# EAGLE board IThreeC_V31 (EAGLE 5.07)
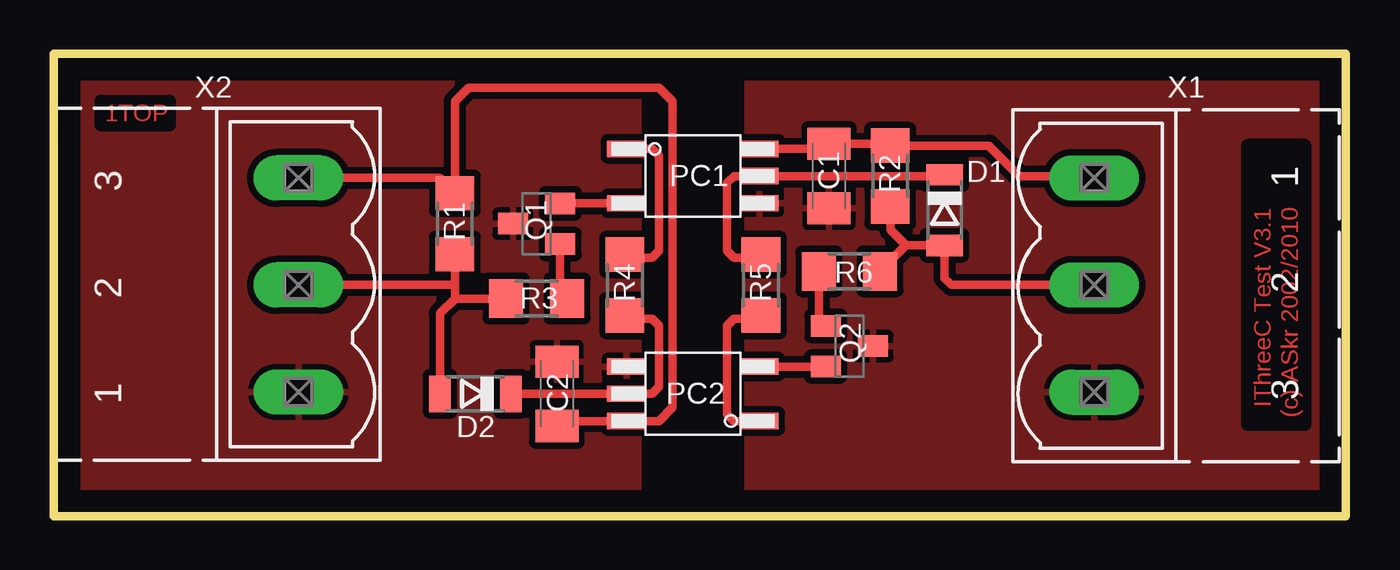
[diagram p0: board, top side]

Size 60.33 x 21.59 mm. Coordinates in mm from the lower left corner, seen from the top.
Outline: 0,21.59 60.33,21.59 60.33,0 0,0 0,21.59
Copper layers (1*16): Top 0.035mm / dielectric 1.5mm / Bottom 0.035mm
Design rules "default": minimum track width 10mil, minimum drill 24mil, track to track 8mil, track to pad 8mil, pad to pad 8mil, via to via 8mil, smd to smd 8mil, copper to edge 40mil, drill to drill 8mil, minimum pad ring 10mil, minimum via ring 8mil, stop-mask expansion 4mil, vias tented up to drill 0mil, thermal gap 10mil
tRestrict: 8 lines

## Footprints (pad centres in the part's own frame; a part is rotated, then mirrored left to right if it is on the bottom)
C1206K = smd 1.5 x 2: 1 -1.5,0; 2 1.5,0
SOD80-R = smd 1 x 1.7: A 1.65,0; C -1.65,0
AKKI_OPTOCOUP6SMD = smd 1.778 x 0.762: 1 -3.111,1.27; 3 -3.111,-1.27; 4 3.111,-1.27; 5 3.111,0; 6 3.111,1.27
SOT23-BEC = smd 1 x 1.4: B -0.95,-1.1; C 0,1.1; E 0.95,-1.1
R1206 = smd 1.6 x 1.803: 1 -1.422,0; 2 1.422,0
AKKI_MSTBV3 = drill 1.397 long: 1 -5,0; 2 0,0; 3 5,0

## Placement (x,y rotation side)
C1  470n  [C1206K]  36.2,15.88 270 top
C2  470n  [C1206K]  23.5,5.71 270 top
D1  LL103  [SOD80-R]  41.59,14.29 270 top
D2  LL103  [SOD80-R]  19.69,5.71 180 top
PC1  TLP102  [AKKI_OPTOCOUP6SMD]  29.85,15.88 0 top
PC2  TLP102  [AKKI_OPTOCOUP6SMD]  29.85,5.71 180 top
Q1  BC807-40  [SOT23-BEC]  22.54,13.65 90 top
Q2  BC807-40  [SOT23-BEC]  37.15,7.94 270 top
R1  (*1*)  [R1206]  18.73,13.65 270 top
R2  (*1*)  [R1206]  39.05,15.88 270 top
R3  5k6  [R1206]  22.54,10.16 180 top
R4  680E  [R1206]  26.67,10.8 90 top
R5  680E  [R1206]  33.02,10.8 90 top
R6  5k6  [R1206]  37.15,11.43 180 top
X1  [AKKI_MSTBV3]  48.58,10.8 270 top
X2  [AKKI_MSTBV3]  11.43,10.8 90 top

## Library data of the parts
C1 C2 R1 R2 = rcl
D1 D2 PC1 PC2 X1 X2 = Akki
Q1 Q2 = transistor-pnp
R3 R6 = rcl; NOTE: (*1*)
R4 R5 = rcl; NOTE: (*2*)

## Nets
+UB: C2.2 PC2.6 R1.1 X2.3
+UB#2: C1.1 PC1.6 R2.1 X1.1
GNDI: C2.1 PC2.4 Q1.C X2.1
GNDO: C1.2 PC1.4 Q2.C X1.3
N$1: PC1.1 R4.2
N$2: D2.C PC2.5 R4.1
N$3: PC1.3 Q1.E
N$4: Q1.B R3.1
N$5: D2.A R1.2 R3.2 X2.2
N$6: D1.C PC1.5 R5.2
N$10: PC2.1 R5.1
N$11: PC2.3 Q2.E
N$12: Q2.B R6.2
N$13: D1.A R2.2 R6.1 X1.2

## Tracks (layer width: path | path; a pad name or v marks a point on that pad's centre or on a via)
+UB
  Top 0.406: C2.2 23.73,4.45 PC2.6 28.26,4.45 28.89,5.08 28.89,19.37 28.26,20 19.37,20 18.73,19.37 R1.1 18.01,15.8 X2.3
+UB#2
  Top 0.406: PC1.6 35.96,17.14 C1.1 38.97,17.38 R2.1 43.66,17.3 45.09,15.88 48.5,15.88 X1.1
GNDI
  pour Top (isolate 0.305): 0.64,20.95 27.3,20.95 27.3,0.63 0.64,0.63
GNDO
  pour Top (isolate 0.305): 32.38,20.95 59.69,20.95 59.69,0.63 32.38,0.63
N$1
  Top 0.406: PC1.1 27.94,17.14 28.26,16.83 28.26,12.38 27.94,12.06 26.82,12.06 R4.2
N$2
  Top 0.406: R4.1 26.84,9.21 27.94,9.21 28.26,8.89 28.26,6.03 27.94,5.71 PC2.5 D2.C
N$3
  Top 0.406: PC1.3 Q1.E
N$4
  Top 0.406: Q1.B 23.64,10.48 R3.1
N$5
  Top 0.406: X2.2 18.73,10.8 | 18.73,10.8 R1.2 | 18.73,10.16 R3.2 | 18.73,10.8 18.73,10.16 | D2.A 18.04,9.46 18.73,10.16
N$6
  Top 0.406: R5.2 32.87,12.06 31.75,12.06 31.43,12.38 31.43,15.56 31.75,15.88 PC1.5 41.53,15.88 D1.C
N$10
  Top 0.406: PC2.1 31.75,4.45 31.43,4.76 31.43,8.89 31.75,9.21 32.85,9.21 R5.1
N$11
  Top 0.406: PC2.3 Q2.E
N$12
  Top 0.406: R6.2 35.72,9.21 Q2.B
N$13
  Top 0.406: X1.2 41.91,10.8 41.59,11.11 D1.A 39.78,12.64 | R6.1 39.78,12.64 | R2.2 39.05,13.36 39.78,12.64

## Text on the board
Top: 1TOP | IThreeC Test V3.1 | (c) ASkr 2002/2010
